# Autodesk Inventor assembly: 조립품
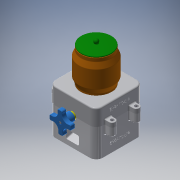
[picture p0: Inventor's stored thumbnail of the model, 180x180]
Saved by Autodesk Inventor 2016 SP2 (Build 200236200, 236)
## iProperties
Created: 2018-01
Part Number: 조립품
Document SubType Name: Assembly
Designer: Administrator
Author: Administrator
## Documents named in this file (9)
- D:\480107V1001\조립품.iam
- D:\480107V1001\본체.ipt
- D:\480107V1001\핸들축.ipt
- D:\480107V1001\본체커버.ipt
- D:\480107V1001\용기.ipt
- D:\480107V1001\용기캡.ipt
- D:\480107V1001\볼트 M4x12.ipt
- D:\480107V1001\핸들.ipt
- D:\480107V1001\볼트 M3x12.ipt
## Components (2 placed, 2 different names)
1. 핸들축:1
2. 핸들:1
